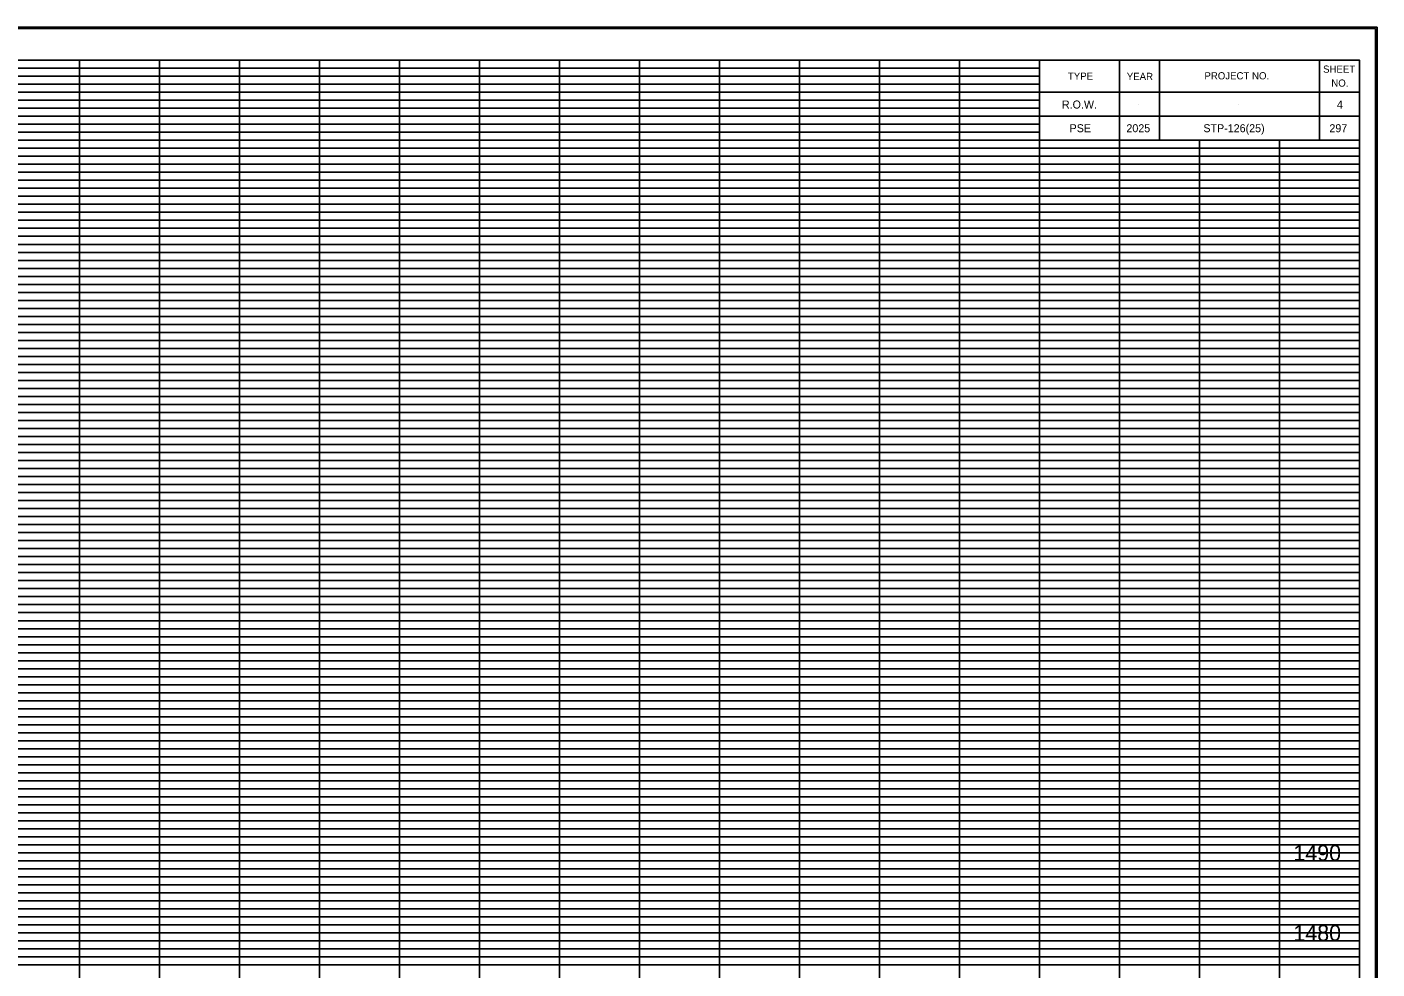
# Model space of a CAD drawing. Extents: x 980 to 2064, y 978 to 2267.
# Drawn here: x 1153.4 to 1322.2, y 1876.5 to 1994.1 of the extents above; entities that cross this region are included whole.
import ezdxf

# ---------------------------------------------------------------- set-up
doc = ezdxf.new("R2010")
doc.units = 0
for name, color, linetype in [('Default', 7, 'Continuous'), ('DESIGN - SCRATCH - User 1', 7, 'Continuous'), ('DESIGN - SHEET - Corner Text', 7, 'Continuous'), ('DESIGN - SHEET - Light Grid', 7, 'Continuous'), ('DESIGN - SHEET - Linework', 7, 'Continuous'), ('DESIGN - SHEET - Plot Shape', 7, 'Continuous')]:
    doc.layers.add(name, color=color, linetype=linetype)

# ---------------------------------------------------------------- blocks, each defined once
blk = doc.blocks.new('XSTSHT')
at = {"layer": 'DESIGN - SCRATCH - User 1'}
for p, q in [((28.5, 20.45), (28.5, 20.45)), ((29.24, 20.45), (29.24, 20.45)), ((30.49, 20.45), (30.49, 20.45)), ((31.74, 20.45), (31.74, 20.45)), ((28.5, 20.15), (28.5, 20.15)), ((29.24, 20.15), (29.24, 20.15)), ((30.49, 20.15), (30.49, 20.15)), ((31.74, 20.15), (31.74, 20.15))]:
    blk.add_line(p, q, dxfattribs=at)
at = {"layer": 'DESIGN - SHEET - Light Grid'}
for p, q in [((8, 20.9), (16, 20.9)), ((8, 20.8), (16, 20.8)), ((16, 20.9), (24, 20.9)), ((16, 20.8), (24, 20.8)), ((24, 20.9), (28, 20.9)), ((24, 20.8), (28, 20.8)), ((8, 20.7), (16, 20.7)), ((8, 20.6), (16, 20.6)), ((16, 20.7), (24, 20.7)), ((16, 20.6), (24, 20.6)), ((24, 20.7), (28, 20.7)), ((24, 20.6), (28, 20.6)), ((8, 20.5), (16, 20.5)), ((16, 20.5), (24, 20.5)), ((24, 20.5), (28, 20.5)), ((8, 20.4), (16, 20.4)), ((8, 20.3), (16, 20.3)), ((16, 20.4), (24, 20.4)), ((16, 20.3), (24, 20.3)), ((24, 20.4), (28, 20.4)), ((24, 20.3), (28, 20.3)), ((8, 20.2), (16, 20.2)), ((8, 20.1), (16, 20.1)), ((16, 20.2), (24, 20.2)), ((16, 20.1), (24, 20.1)), ((24, 20.2), (28, 20.2)), ((24, 20.1), (28, 20.1)), ((8, 19.9), (16, 19.9)), ((8, 19.8), (16, 19.8)), ((16, 19.9), (24, 19.9)), ((16, 19.8), (24, 19.8)), ((24, 19.9), (32, 19.9)), ((24, 19.8), (32, 19.8)), ((8, 19.7), (16, 19.7)), ((8, 19.6), (16, 19.6)), ((16, 19.7), (24, 19.7)), ((16, 19.6), (24, 19.6)), ((24, 19.7), (32, 19.7)), ((24, 19.6), (32, 19.6)), ((8, 19.5), (16, 19.5)), ((16, 19.5), (24, 19.5)), ((24, 19.5), (32, 19.5)), ((8, 19.4), (16, 19.4)), ((8, 19.3), (16, 19.3)), ((16, 19.4), (24, 19.4)), ((16, 19.3), (24, 19.3)), ((24, 19.4), (32, 19.4)), ((24, 19.3), (32, 19.3)), ((8, 19.2), (16, 19.2)), ((8, 19.1), (16, 19.1)), ((16, 19.2), (24, 19.2)), ((16, 19.1), (24, 19.1)), ((24, 19.2), (32, 19.2)), ((24, 19.1), (32, 19.1)), ((8, 18.9), (16, 18.9)), ((16, 18.9), (24, 18.9)), ((24, 18.9), (32, 18.9)), ((8, 18.8), (16, 18.8)), ((16, 18.8), (24, 18.8)), ((24, 18.8), (32, 18.8)), ((8, 18.7), (16, 18.7)), ((8, 18.6), (16, 18.6)), ((16, 18.7), (24, 18.7)), ((16, 18.6), (24, 18.6)), ((24, 18.7), (32, 18.7)), ((24, 18.6), (32, 18.6)), ((8, 18.5), (16, 18.5)), ((8, 18.4), (16, 18.4)), ((16, 18.5), (24, 18.5)), ((16, 18.4), (24, 18.4)), ((24, 18.5), (32, 18.5)), ((24, 18.4), (32, 18.4)), ((8, 18.3), (16, 18.3)), ((16, 18.3), (24, 18.3)), ((24, 18.3), (32, 18.3)), ((8, 18.2), (16, 18.2)), ((8, 18.1), (16, 18.1)), ((16, 18.2), (24, 18.2)), ((16, 18.1), (24, 18.1)), ((24, 18.2), (32, 18.2)), ((24, 18.1), (32, 18.1)), ((8, 17.9), (16, 17.9)), ((16, 17.9), (24, 17.9)), ((24, 17.9), (32, 17.9)), ((8, 17.8), (16, 17.8)), ((16, 17.8), (24, 17.8)), ((24, 17.8), (32, 17.8)), ((8, 17.7), (16, 17.7)), ((8, 17.6), (16, 17.6)), ((16, 17.7), (24, 17.7)), ((16, 17.6), (24, 17.6)), ((24, 17.7), (32, 17.7)), ((24, 17.6), (32, 17.6)), ((8, 17.5), (16, 17.5)), ((8, 17.4), (16, 17.4)), ((16, 17.5), (24, 17.5)), ((16, 17.4), (24, 17.4)), ((24, 17.5), (32, 17.5)), ((24, 17.4), (32, 17.4)), ((8, 17.3), (16, 17.3)), ((16, 17.3), (24, 17.3)), ((24, 17.3), (32, 17.3)), ((8, 17.2), (16, 17.2)), ((8, 17.1), (16, 17.1)), ((16, 17.2), (24, 17.2)), ((16, 17.1), (24, 17.1)), ((24, 17.2), (32, 17.2)), ((24, 17.1), (32, 17.1)), ((8, 16.9), (16, 16.9)), ((16, 16.9), (24, 16.9)), ((24, 16.9), (32, 16.9)), ((8, 16.8), (16, 16.8)), ((16, 16.8), (24, 16.8)), ((24, 16.8), (32, 16.8)), ((8, 16.7), (16, 16.7)), ((8, 16.6), (16, 16.6)), ((16, 16.7), (24, 16.7)), ((16, 16.6), (24, 16.6)), ((24, 16.7), (32, 16.7)), ((24, 16.6), (32, 16.6)), ((8, 16.5), (16, 16.5)), ((8, 16.4), (16, 16.4)), ((16, 16.5), (24, 16.5)), ((16, 16.4), (24, 16.4)), ((24, 16.5), (32, 16.5)), ((24, 16.4), (32, 16.4)), ((8, 16.3), (16, 16.3)), ((8, 16.2), (16, 16.2)), ((16, 16.3), (24, 16.3)), ((16, 16.2), (24, 16.2)), ((24, 16.3), (32, 16.3)), ((24, 16.2), (32, 16.2)), ((8, 16.1), (16, 16.1)), ((16, 16.1), (24, 16.1)), ((24, 16.1), (32, 16.1)), ((8, 15.9), (16, 15.9)), ((16, 15.9), (24, 15.9)), ((24, 15.9), (32, 15.9)), ((8, 15.8), (16, 15.8)), ((8, 15.7), (16, 15.7)), ((16, 15.8), (24, 15.8)), ((16, 15.7), (24, 15.7)), ((24, 15.8), (32, 15.8)), ((24, 15.7), (32, 15.7)), ((8, 15.6), (16, 15.6)), ((16, 15.6), (24, 15.6)), ((24, 15.6), (32, 15.6)), ((8, 15.5), (16, 15.5)), ((8, 15.4), (16, 15.4)), ((16, 15.5), (24, 15.5)), ((16, 15.4), (24, 15.4)), ((24, 15.5), (32, 15.5)), ((24, 15.4), (32, 15.4)), ((8, 15.3), (16, 15.3)), ((8, 15.2), (16, 15.2)), ((16, 15.3), (24, 15.3)), ((16, 15.2), (24, 15.2)), ((24, 15.3), (32, 15.3)), ((24, 15.2), (32, 15.2)), ((8, 15.1), (16, 15.1)), ((16, 15.1), (24, 15.1)), ((24, 15.1), (32, 15.1)), ((8, 14.9), (16, 14.9)), ((16, 14.9), (24, 14.9)), ((24, 14.9), (32, 14.9)), ((8, 14.8), (16, 14.8)), ((8, 14.7), (16, 14.7)), ((16, 14.8), (24, 14.8)), ((16, 14.7), (24, 14.7)), ((24, 14.8), (32, 14.8)), ((24, 14.7), (32, 14.7)), ((8, 14.6), (16, 14.6)), ((16, 14.6), (24, 14.6)), ((24, 14.6), (32, 14.6)), ((8, 14.5), (16, 14.5)), ((8, 14.4), (16, 14.4)), ((16, 14.5), (24, 14.5)), ((16, 14.4), (24, 14.4)), ((24, 14.5), (32, 14.5)), ((24, 14.4), (32, 14.4)), ((8, 14.3), (16, 14.3)), ((8, 14.2), (16, 14.2)), ((16, 14.3), (24, 14.3)), ((16, 14.2), (24, 14.2)), ((24, 14.3), (32, 14.3)), ((24, 14.2), (32, 14.2)), ((8, 14.1), (16, 14.1)), ((16, 14.1), (24, 14.1)), ((24, 14.1), (32, 14.1)), ((8, 13.9), (16, 13.9)), ((16, 13.9), (24, 13.9)), ((24, 13.9), (32, 13.9)), ((8, 13.8), (16, 13.8)), ((8, 13.7), (16, 13.7)), ((16, 13.8), (24, 13.8)), ((16, 13.7), (24, 13.7)), ((24, 13.8), (32, 13.8)), ((24, 13.7), (32, 13.7)), ((8, 13.6), (16, 13.6)), ((8, 13.5), (16, 13.5)), ((16, 13.6), (24, 13.6)), ((16, 13.5), (24, 13.5)), ((24, 13.6), (32, 13.6)), ((24, 13.5), (32, 13.5)), ((8, 13.4), (16, 13.4)), ((16, 13.4), (24, 13.4)), ((24, 13.4), (32, 13.4)), ((8, 13.3), (16, 13.3)), ((8, 13.2), (16, 13.2)), ((16, 13.3), (24, 13.3)), ((16, 13.2), (24, 13.2)), ((24, 13.3), (32, 13.3)), ((24, 13.2), (32, 13.2)), ((8, 13.1), (16, 13.1)), ((16, 13.1), (24, 13.1)), ((24, 13.1), (32, 13.1)), ((8, 12.9), (16, 12.9)), ((16, 12.9), (24, 12.9)), ((24, 12.9), (32, 12.9)), ((8, 12.8), (16, 12.8)), ((8, 12.7), (16, 12.7)), ((16, 12.8), (24, 12.8)), ((16, 12.7), (24, 12.7)), ((24, 12.8), (32, 12.8)), ((24, 12.7), (32, 12.7)), ((8, 12.6), (16, 12.6)), ((8, 12.5), (16, 12.5)), ((16, 12.6), (24, 12.6)), ((16, 12.5), (24, 12.5)), ((24, 12.6), (32, 12.6)), ((24, 12.5), (32, 12.5)), ((8, 12.4), (16, 12.4)), ((16, 12.4), (24, 12.4)), ((24, 12.4), (32, 12.4)), ((8, 12.3), (16, 12.3)), ((8, 12.2), (16, 12.2)), ((16, 12.3), (24, 12.3)), ((16, 12.2), (24, 12.2)), ((24, 12.3), (32, 12.3)), ((24, 12.2), (32, 12.2)), ((8, 12.1), (16, 12.1)), ((16, 12.1), (24, 12.1)), ((24, 12.1), (32, 12.1)), ((8, 11.9), (16, 11.9)), ((16, 11.9), (24, 11.9)), ((24, 11.9), (32, 11.9)), ((8, 11.8), (16, 11.8)), ((8, 11.7), (16, 11.7)), ((16, 11.8), (24, 11.8)), ((16, 11.7), (24, 11.7)), ((24, 11.8), (32, 11.8)), ((24, 11.7), (32, 11.7)), ((8, 11.6), (16, 11.6)), ((8, 11.5), (16, 11.5)), ((16, 11.6), (24, 11.6)), ((16, 11.5), (24, 11.5)), ((24, 11.6), (32, 11.6)), ((24, 11.5), (32, 11.5)), ((8, 11.4), (16, 11.4)), ((16, 11.4), (24, 11.4)), ((24, 11.4), (32, 11.4)), ((8, 11.3), (16, 11.3)), ((8, 11.2), (16, 11.2)), ((16, 11.3), (24, 11.3)), ((16, 11.2), (24, 11.2)), ((24, 11.3), (32, 11.3)), ((24, 11.2), (32, 11.2)), ((8, 11.1), (16, 11.1)), ((16, 11.1), (24, 11.1)), ((24, 11.1), (32, 11.1)), ((8, 10.9), (16, 10.9)), ((8, 10.8), (16, 10.8)), ((16, 10.9), (24, 10.9)), ((16, 10.8), (24, 10.8)), ((24, 10.9), (32, 10.9)), ((24, 10.8), (32, 10.8)), ((8, 10.7), (16, 10.7)), ((16, 10.7), (24, 10.7)), ((24, 10.7), (32, 10.7)), ((8, 10.6), (16, 10.6)), ((8, 10.5), (16, 10.5)), ((16, 10.6), (24, 10.6)), ((16, 10.5), (24, 10.5)), ((24, 10.6), (32, 10.6)), ((24, 10.5), (32, 10.5)), ((8, 10.4), (16, 10.4)), ((8, 10.3), (16, 10.3)), ((16, 10.4), (24, 10.4)), ((16, 10.3), (24, 10.3)), ((24, 10.4), (32, 10.4)), ((24, 10.3), (32, 10.3)), ((8, 10.2), (16, 10.2)), ((16, 10.2), (24, 10.2)), ((24, 10.2), (32, 10.2)), ((8, 10.1), (16, 10.1)), ((16, 10.1), (24, 10.1)), ((24, 10.1), (32, 10.1)), ((8, 9.9), (16, 9.9)), ((8, 9.8), (16, 9.8)), ((16, 9.9), (24, 9.9)), ((16, 9.8), (24, 9.8)), ((24, 9.9), (32, 9.9)), ((24, 9.8), (32, 9.8)), ((8, 9.7), (16, 9.7)), ((16, 9.7), (24, 9.7)), ((24, 9.7), (32, 9.7))]:
    blk.add_line(p, q, dxfattribs=at)
at = {"layer": 'DESIGN - SHEET - Linework'}
for p, q in [((-1.823, 21.414), (32.217, 21.414)), ((32.217, 21.414), (32.217, -0.414)), ((16, 0), (16, 21)), ((17, 0), (17, 21)), ((18, 0), (18, 21)), ((19, 0), (19, 21)), ((20, 0), (20, 21)), ((21, 0), (21, 21)), ((22, 0), (22, 21)), ((23, 0), (23, 21)), ((24, 0), (24, 21)), ((25, 0), (25, 21)), ((26, 0), (26, 21)), ((27, 0), (27, 21)), ((0, 20), (28, 20)), ((28, 0), (28, 20)), ((29, 0), (29, 20)), ((30, 0), (30, 20)), ((31, 0), (31, 20)), ((0, 19), (32, 19)), ((0, 18), (32, 18)), ((0, 17), (32, 17)), ((0, 16), (32, 16)), ((0, 15), (32, 15)), ((0, 14), (32, 14)), ((0, 13), (32, 13)), ((0, 12), (32, 12)), ((0, 11), (32, 11)), ((0, 10), (32, 10))]:
    blk.add_line(p, q, dxfattribs=at)
for points in [[(0, 21), (0, 0), (32, 0), (32, 21), (0, 21)], [(28, 21), (28, 20), (32, 20), (32, 21), (31.5, 21), (31.5, 20), (29.5, 20), (29.5, 21), (29, 21), (29, 20), (32, 20), (28, 20), (28, 20.3), (32, 20.3), (32, 20.6), (28, 20.6)]]:
    blk.add_lwpolyline(points, dxfattribs=at)
at = {"layer": 'DESIGN - SHEET - Plot Shape'}
for points in [[(-1.803, 21.394), (32.197, 21.394), (32.197, -0.394), (-1.803, -0.394)], [(-0.85, 21), (32, 21), (32, -0.25), (-0.85, -0.25)]]:
    blk.add_lwpolyline(points, close=True, dxfattribs=at)
at = {"layer": 'DESIGN - SHEET - Corner Text'}
for s, p in [('SHEET', (31.543, 20.843)), ('TYPE', (28.354, 20.756)), ('YEAR', (29.09, 20.752)), ('PROJECT NO.', (30.06, 20.76)), ('NO.', (31.646, 20.669))]:
    blk.add_text(s, height=0.09, dxfattribs=at).set_placement(p)

msp = doc.modelspace()

# ---------------------------------------------------------------- block references
at = {"layer": 'Default', "xscale": 10, "yscale": 10}
msp.add_blockref('XSTSHT', (1000, 1780), dxfattribs=at)

# ---------------------------------------------------------------- texts
at = {"layer": 'Default'}
for s, p in [('     1490     ', (1308.01, 1890)), ('     1480     ', (1308.01, 1880))]:
    msp.add_text(s, height=2, dxfattribs=at).set_placement(p)
at = {"layer": 'DESIGN - SHEET - Corner Text'}
for s, p in [('R.O.W.', (1282.79, 1983.96)), ('4', (1317.16, 1983.96)), ('PSE', (1283.75, 1981)), ('2025', (1290.85, 1981)), ('STP-126(25)', (1300.47, 1981)), ('297', (1316.22, 1981))]:
    msp.add_text(s, height=1, dxfattribs=at).set_placement(p)

doc.saveas('drawing.dxf')
